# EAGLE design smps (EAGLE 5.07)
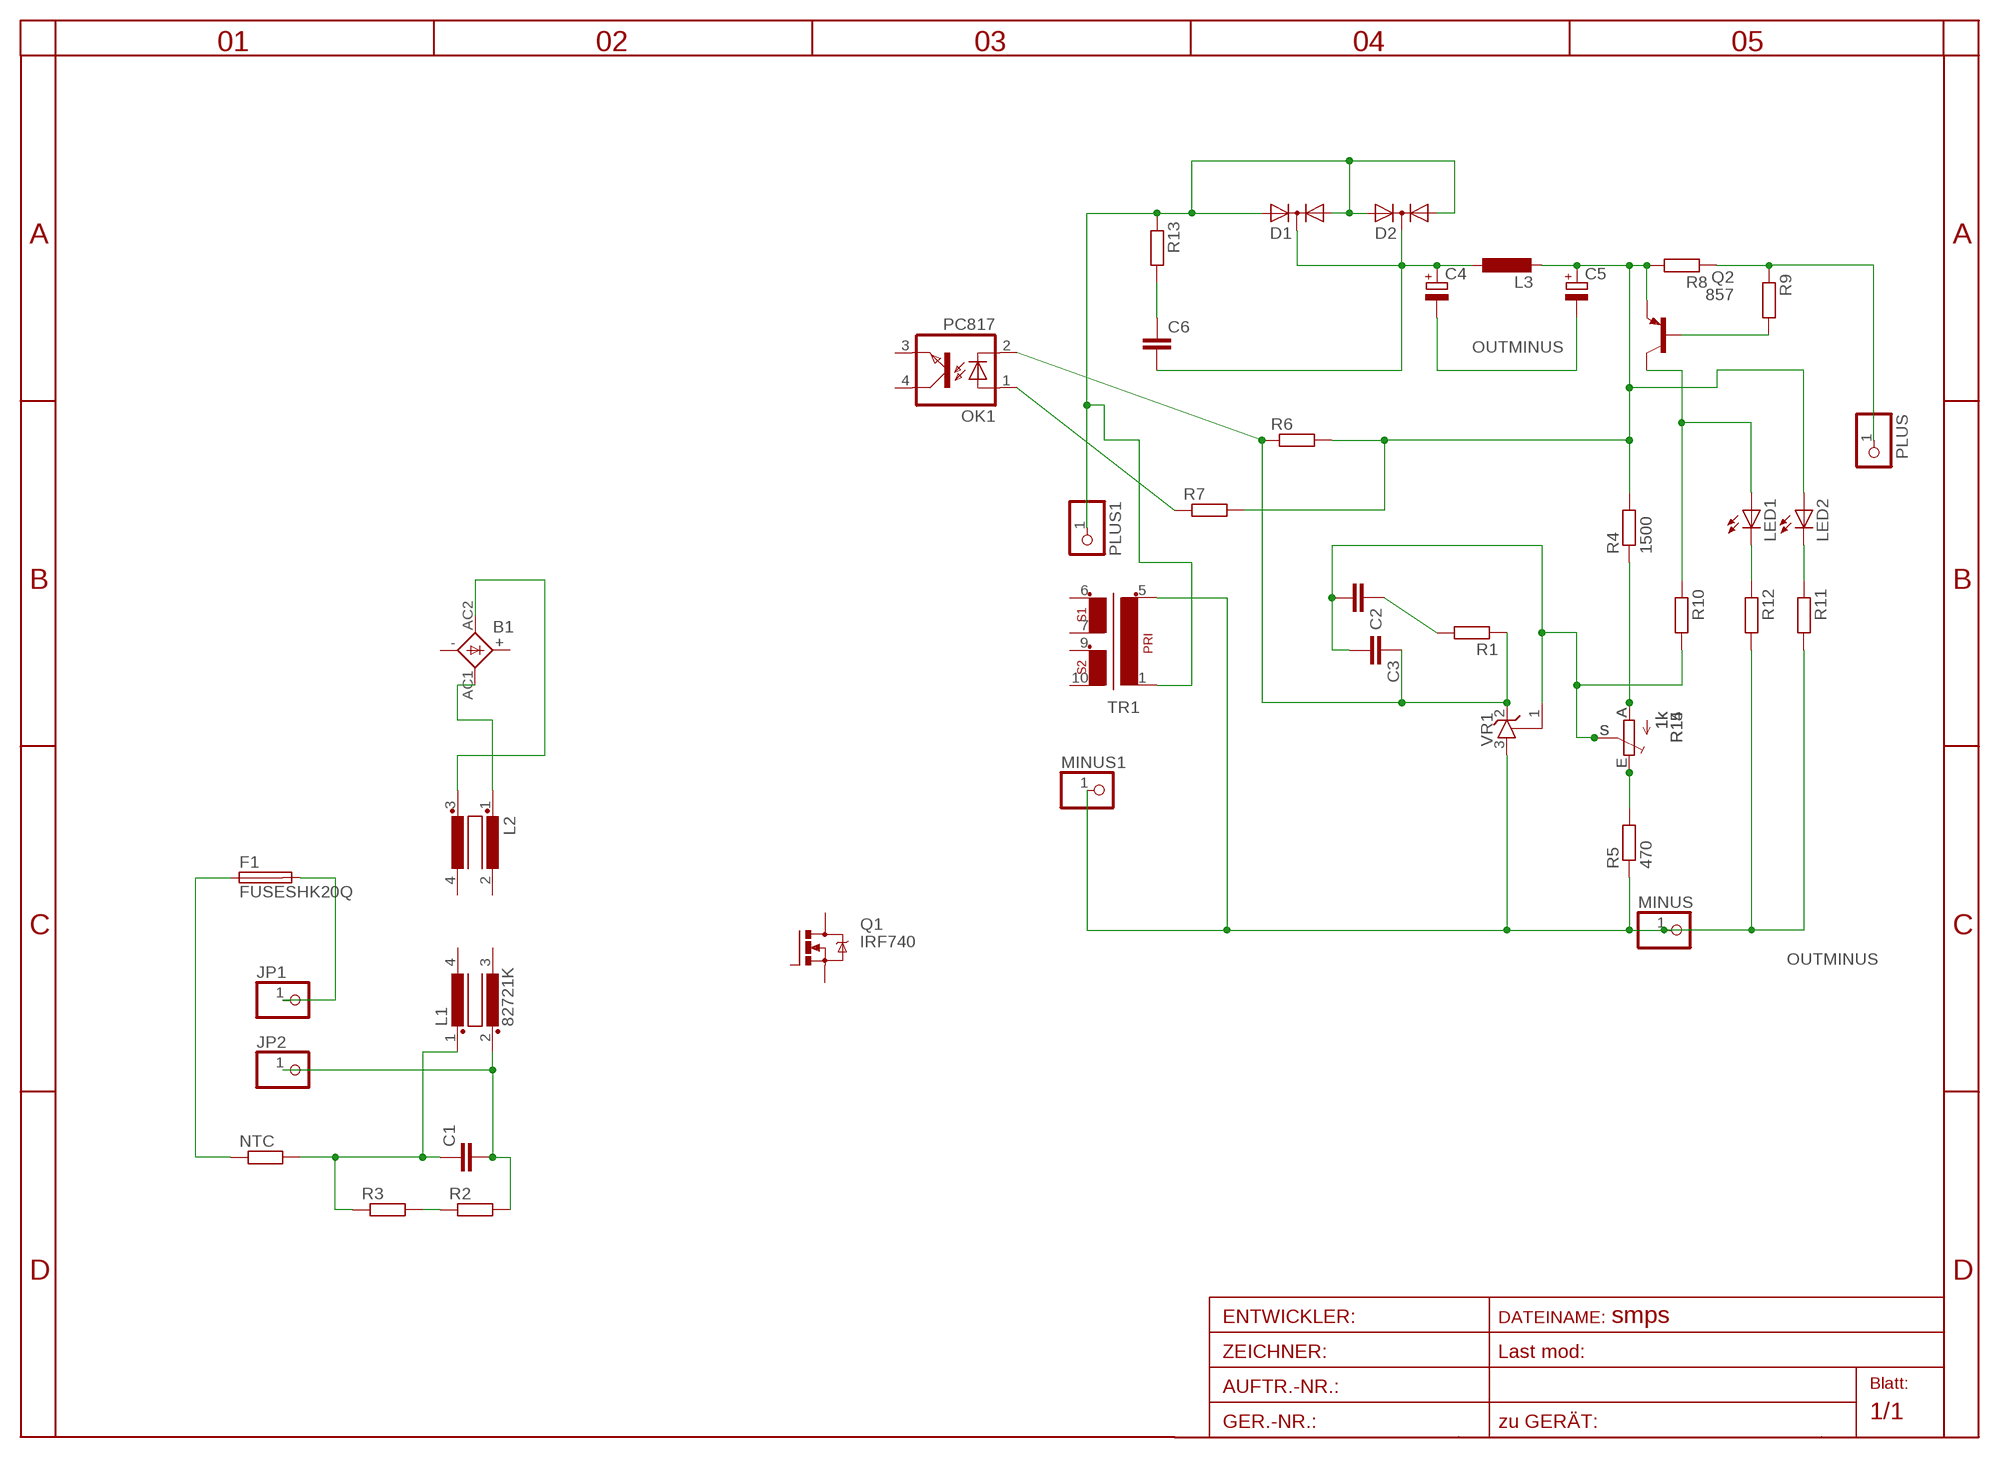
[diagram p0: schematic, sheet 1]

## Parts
B1  KBL  [KBL]
C1  C-EU150-084X183  [C150-084X183]
C2  C-EUC0805  [C0805]
C3  C-EUC0805  [C0805]
C4  CPOL-EUE5-8.5  [E5-8,5]
C5  CPOL-EUE5-8.5  [E5-8,5]
C6  C-EUC1206  [C1206]
D1  DIODE-2AC|CAIW220V  [IW220ABS]
D2  DIODE-2AC|CAIW220V  [IW220ABS]
F1  FUSESHK20Q  [SHK20Q]
JP1  PINHD-1X12MM2  [1X2MM2]
JP2  PINHD-1X12MM2  [1X2MM2]
L1  82721K  [82721K]
L2  R1405VB1  [B1]
L3  L-EU0204/5  [0204/5]
LED1  LED3MM  [LED3MM]
LED2  LED3MM  [LED3MM]
MINUS  PINHD-1X12MM2  [1X2MM2]
MINUS1  PINHD-1X11X0.4  [1X01]
NTC  R-EU_0204/7  [0204/7]
OK1  PC817  [DIL04]
PLUS  PINHD-1X12MM2  [1X2MM2]
PLUS1  PINHD-1X11X0.4  [1X01]
Q1  IRF740  [TO220BV]
Q2  857  BC857ASMD  [SOT23-BEC]
R1  R-EU_R0805  [R0805]
R2  R-EU_R1206  [R1206]
R3  R-EU_R1206  [R1206]
R4  1500  R-EU_R0805  [R0805]
R5  470  R-EU_R0805  [R0805]
R6  R-EU_R0805  [R0805]
R7  R-EU_R0805  [R0805]
R8  R-EU_R2010  [R2010]
R9  R-EU_R0805  [R0805]
R10  R-EU_R0805  [R0805]
R11  R-EU_R0805  [R0805]
R12  R-EU_R0805  [R0805]
R13  R-EU_R1206  [R1206]
R14  1k  TRIM_EU-S64W  [S64W]
R15  1k  TRIM_EU-CA6V  [CA6V]
TR1  EE20-2  [EE30GREEN]
VR1  TL431CLPSOT23  [SOT23]

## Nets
A: R4.1 R14.A R15.A
C1: LED1.A Q2.C R10.1
CPLUS: C4.+ C6.2 D1.C D2.C L3.1
E: R5.2 R14.E R15.E
N$1: C1.2 JP2.1 L1.2 R2.2
N$2: C1.1 L1.1 NTC.2 R3.1
N$3: F1.2A JP1.1
N$6: R2.1 R3.2
N$7: B1.AC2(AC1) L2.3
N$8: B1.AC1(AC2) L2.1
N$9: F1.1A NTC.1
N$11: C3.1 OK1.2(C) R1.1 R6.1 VR1.2(C)
N$12: OK1.1(A) R7.1
N$13: C2.1 R1.2
N$16: Q2.B R9.2
N$21: LED1.K(C) R12.1
N$23: LED2.K(C) R11.1
N$27: C6.1 R13.2
OUTMINUS: C4.- C5.- MINUS1.1 MINUS.1 R5.1 R11.2 R12.2 TR1.5 VR1.3(A)
OUTPLUS: PLUS.1 R8.1 R9.1
PLUS2: C5.+ L3.2 LED2.A Q2.E R4.2 R6.2 R7.2 R8.2
S: C2.2 C3.2 R10.2 R14.S R15.S VR1.1(R)
TOUT: D1.A1 D1.A2 D2.A1 D2.A2 PLUS1.1 R13.1 TR1.1
Unconnected: B1.+ B1.- L1.3 L1.4 L2.2 L2.4 OK1.3(EMIT) OK1.4(COL) Q1.D Q1.G Q1.S TR1.6 TR1.7 TR1.9 TR1.10

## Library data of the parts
B1 = rectifier:KBL: DIOTEC RECTIFIER
C1-C3 C6 = rcl:C-EU: CAPACITOR, European symbol
C4 C5 = rcl:CPOL-EU: POLARIZED CAPACITOR, European symbol
D1 D2 = diode:DIODE-2AC|CA: Dual DIODE Anode-Cathode|Cathode-Anode
F1 = fuse:FUSE: Fuse
JP1 JP2 MINUS MINUS1 PLUS PLUS1 = pinhead:PINHD-1X1: PIN HEADER
L1 = inductors:82721K: FILTER
L2 = inductor-nkl:R1405V: Übertrager (verlustarm) bis typ. 400kHz Power transformer (low loss) up to typ. 400kHz
L3 = rcl:L-EU: INDUCTOR, European symbol
LED1 LED2 = led:LED: LED
NTC R1-R13 = rcl:R-EU_: RESISTOR, European symbol
OK1 = optocoupler:PC817: SHARP OPTO COUPLER
Q1 = transistor-power:IRF740: N-CHANNEL MOS FET
Q2 = transistor-pnp:BC857*: PNP Transistror
R14 R15 = pot:TRIM_EU-: POTENTIOMETER
TR1 = trafo:EE20-2: TRANSFORMER 1 primary winding, 2 secondary windings ERA
VR1 = v-reg:TL431CLP: VOLTAGE REGULATOR

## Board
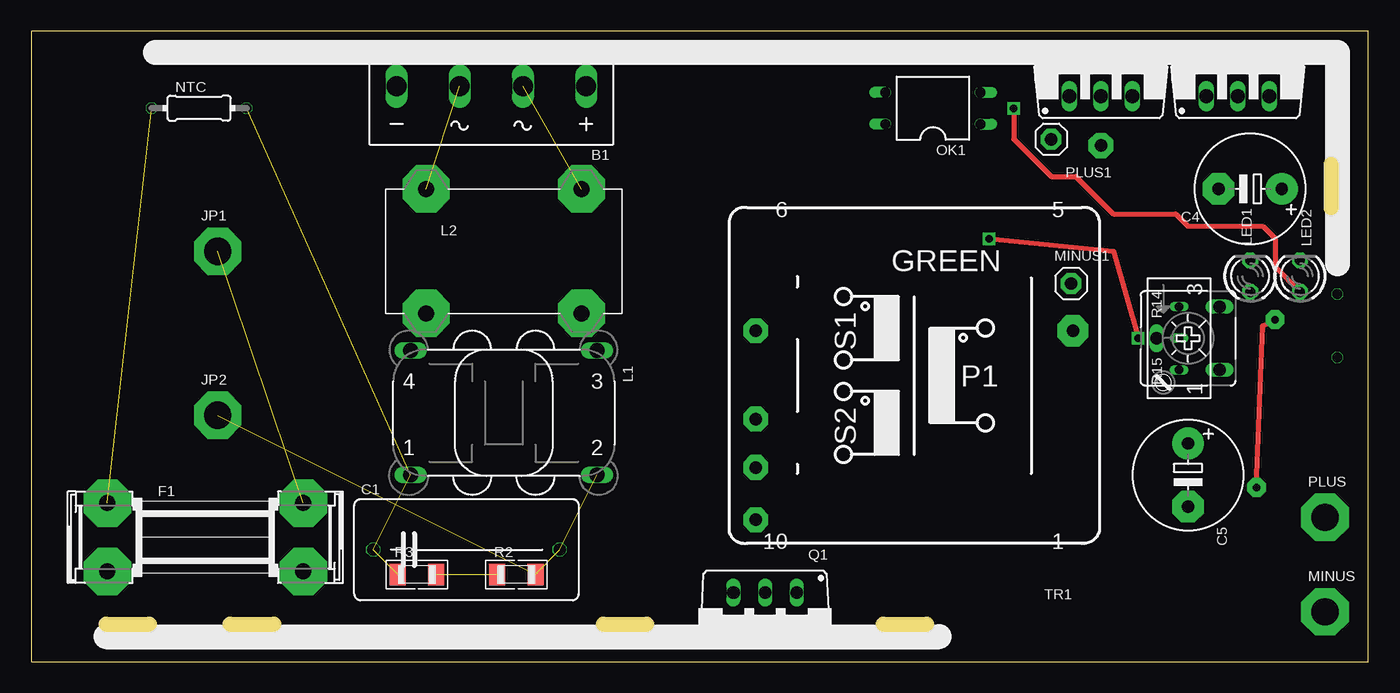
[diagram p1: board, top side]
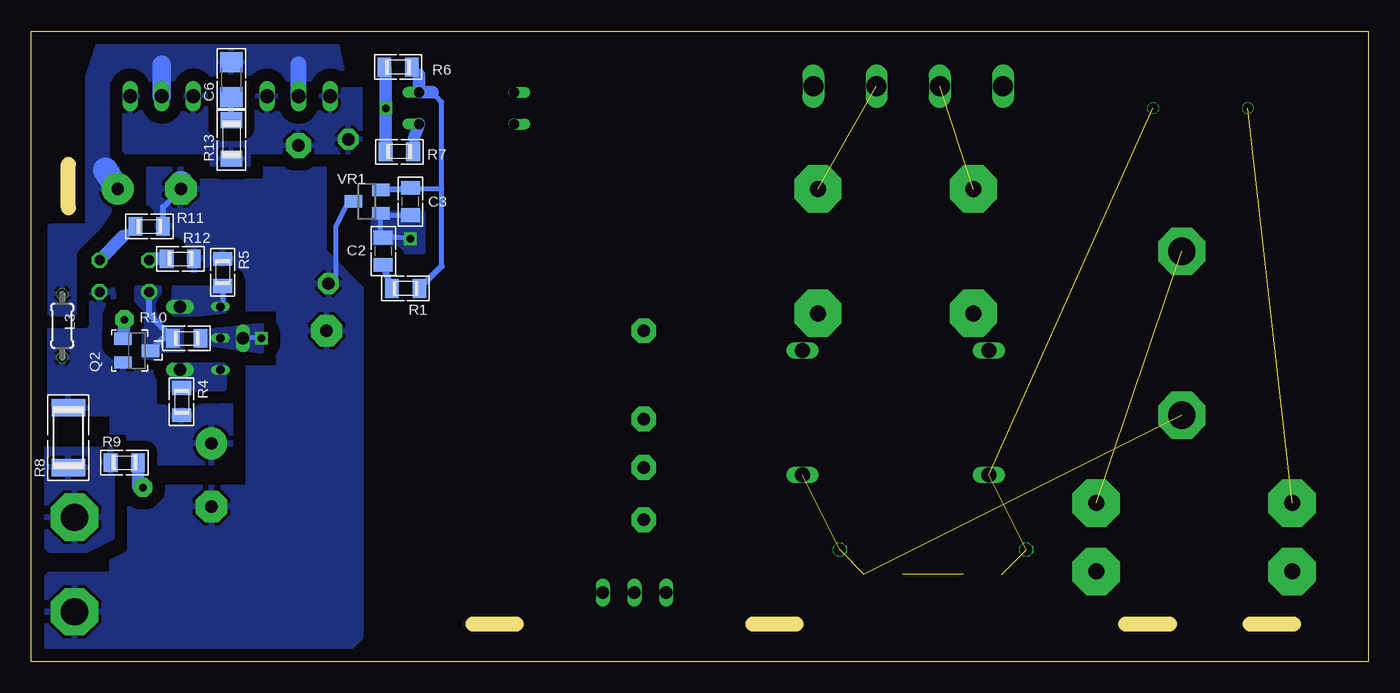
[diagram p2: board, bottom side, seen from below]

Size 107.5 x 50.7 mm. Coordinates in mm from the lower left corner, seen from the top.
Outline: 0,0 107.5,0 107.5,50.7 0,50.7 0,0
Copper layers (1*16): Top 0.035mm / dielectric 1.5mm / Bottom 0.035mm
Design rules "default": minimum track width 10mil, minimum drill 20mil, track to track 8mil, track to pad 8mil, pad to pad 8mil, via to via 8mil, smd to smd 8mil, copper to edge 40mil, drill to drill 8mil, minimum pad ring 1mil, minimum via ring 8mil, stop-mask expansion 4mil, vias tented up to drill 0mil, thermal gap 10mil
Milling: 5 lines

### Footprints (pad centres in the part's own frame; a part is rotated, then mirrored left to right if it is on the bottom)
KBL = drill 1.6 long: + -7.62,-1.27; - 7.62,-1.27; AC1 2.54,-1.27; AC2 -2.54,-1.27
C150-084X183 = drill 1.016 octagon: 1 -7.493,0; 2 7.493,0
C0805 = smd 1.1 x 1.5: 1 -1.1,0; 2 1.1,0
E5-8,5 = drill 1 pad 2.54 round: + -2.54,0 | drill 1 pad 2.54 octagon: - 2.54,0
C1206 = smd 1.6 x 1.8: 1 -1.4,0; 2 1.4,0
IW220ABS = drill 1.118 long: A1 -2.54,-2.54; A2 2.54,-2.54; C 0,-2.54
SHK20Q = drill 1.3 pad 3.81 octagon: 1A -7.874,2.75; 1B -7.874,-2.75; 2A 7.874,2.75; 2B 7.874,-2.75
1X2MM2 = drill 2.2 pad 3.81 octagon: 1 0,0
82721K = drill 1.194 long: 1 7.493,5.004; 2 -7.493,5.004; 3 -7.493,-5.004; 4 7.493,-5.004
B1 = drill 1.27 pad 3.81 octagon: 1 -6.25,5; 2 -6.25,-5; 3 6.25,5; 4 6.25,-5
0204/5 = drill 0.813 octagon: 1 -2.54,0; 2 2.54,0
LED3MM = drill 0.8 pad 1.27 octagon: A -1.27,0; K 1.27,0
1X01 = drill 1 pad 1.676 octagon: 1 0,0
0204/7 = drill 0.813 octagon: 1 -3.81,0; 2 3.81,0
DIL04 = drill 0.813 offset: 1 -1.27,-3.81; 2 1.27,-3.81; 3 1.27,3.81; 4 -1.27,3.81
TO220BV = drill 1.016 long: D 0,-2.54; G -2.54,-2.54; S 2.54,-2.54
SOT23-BEC = smd 1 x 1.4: B -0.95,-1.1; C 0,1.1; E 0.95,-1.1
R0805 = smd 1.1 x 1.5: 1 -1.1,0; 2 1.1,0
R1206 = smd 1.3 x 1.7: 1 -1.55,0; 2 1.55,0
R2010 = smd 1.4 x 2.7: 1 -2.4,0; 2 2.4,0
S64W = drill 0.7 long: A 2.54,1.27; E -2.54,1.27; S 0,1.27
CA6V = drill 1.016 long: A -2.54,-2.54; E 2.54,-2.54; S 0,2.54
EE30GREEN = drill 1 pad 2 octagon: 1 15,18.5; 6 -12.75,3.6; 7 -12.75,-3.5; 9 -12.75,-7.4; 10 -12.75,-11.6 | drill 1 pad 2.5 octagon: 5 12.75,3.6
SOT23 = smd 1 x 1.4: 1 -0.95,-1.1; 2 0.95,-1.1; 3 0,1.1

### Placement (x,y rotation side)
B1  37,45 180 top
C1  35,9 0 top
C2  79.2,33 90 bottom
C3  77,37 270 bottom
C4  98,38 180 top
C5  93,15 270 top
C6  91.4,46.8 90 bottom
D1  97,48 0 top
D2  86,48 0 top
F1  14,10 0 top
JP1  15,33 0 top
JP2  15,19.8 0 top
L1  38,20 180 top
L2  38,33 0 top
L3  105,27 270 bottom
LED1  98,31 90 top
LED2  102,31 90 top
MINUS  104,4 0 top
MINUS1  83.6,30.4 0 top
NTC  13.5,44.5 0 top
OK1  72.5,44.5 90 top
PLUS  104,11.6 0 top
PLUS1  82,42 0 top
Q1  59,3 180 top
Q2  99,25 270 bottom
R1  77.4,30 180 bottom
R2  39,7 0 top
R3  31,7 0 top
R4  95.4,20.9 270 bottom
R5  92.1,31.3 270 bottom
R6  78,47.8 180 bottom
R7  77.9,41 180 bottom
R8  104.5,18 90 bottom
R9  100,16 0 bottom
R10  95,26 0 bottom
R11  98,35 0 bottom
R12  95.5,32.4 0 bottom
R13  91.4,42 90 bottom
R14  91,26 270 top
R15  93,26 90 top
TR1  71,23 0 top
VR1  80.5,37 90 bottom

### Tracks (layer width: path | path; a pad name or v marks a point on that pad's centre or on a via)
A
  pour Bottom (isolate 1.016, rank 2, no thermals): 92,23.8 96.2,23.8 96.2,21.9 92,22
C1
  Bottom 0.5: LED1.A 98,27.9 R10.1 96.9,26 Q2.C
  pour Bottom (isolate 0.8, rank 5, no thermals): 97,30 99,30 99,24 95,24 95,27 97,27
CPLUS
  Bottom 1.27: D2.C 86,48
  Bottom 1.5: D1.C 97,48
  Bottom 2: C4.+ 101.54,39.54
  pour Bottom (isolate 1, rank 3): 83,50 102,50 103,47 103,35 106,35 106,28 104,28 104,33 102,35 100,38 101.1,45.8 82.1,45.8
E
  Bottom 0.406: R5.2 92.1,28.71 R14.E
  pour Bottom (isolate 1, rank 2, no thermals): 96,28 92,28 92,30 96,30
N$1  (3 unrouted)
N$2  (3 unrouted)
N$3  (1 unrouted)
N$6  (1 unrouted)
N$7  (1 unrouted)
N$8  (1 unrouted)
N$9  (1 unrouted)
N$11
  Bottom 0.406: 77.15,37.95 C3.1 76.9,38 74.5,38 | 74.5,31.8 74.5,38 | 76.31,47.21 R6.1 | 75.23,45.77 74.5,45 74.5,38
  Bottom 0.5: 77.15,37.95 VR1.2 | R1.1 74.5,31.8
  Bottom 1: 76.31,47.21 OK1.2 75.23,45.77
N$12
  Bottom 0.5: R7.1 76.7,42.14
  Bottom 1: 76.7,42.14 OK1.1
N$13
  Bottom 0.5: R1.2 C2.1
N$16  (via drill 0.6 pad 1.5)
  Top 0.406: v98.5,14 99,27 v100,27.5
  Bottom 0.406: v98.5,14 98.9,14.1 | v100,27.5 100,27.05
  Bottom 1: 98.9,14.1 R9.2 | 100,27.05 Q2.B
N$21
  Bottom 0.406: 97.87,32.4 LED1.K
  Bottom 1: R12.1 97.87,32.4
N$23
  Bottom 0.5: R11.1 100.1,34.2
  Bottom 1: 100.1,34.2 LED2.K
N$27
  Bottom 0.5: R13.2 C6.1
OUTMINUS
  Bottom 0.406: VR1.3 82,37 83,35 83,31 MINUS1.1
  Bottom 0.5: R11.2 96.9,36.56 C4.-
  Bottom 2: C4.- 95.46,38.46
  pour Bottom (isolate 1, rank 3): 98,40 84,40 84,33 81,30 81,2 82,1 106,1 107,2 107,6 106,7 101,7 101,14 90,14 90,31 96,31 98,36
OUTPLUS
  pour Bottom (isolate 1): 107,17 107,10 106,9 103,9 101,10 101,17
PLUS2  (via drill 0.6)
  Top 0.406: v79,44.5 79,42 82,39 84,39 87,36 92,36 93,35 99,35 100,34 100,31.73 LED2.A
  Bottom 0.406: 79,47.7 R6.2
  Bottom 0.5: R4.2 95.9,20
  Bottom 1: R7.2 v79,44.5 79,47.7
  pour Bottom (isolate 1, rank 4): 102,30 106,27 106,21 105,20 101,20 101,16 91,16 90.7,23.7 99.7,23.5 101,30
S  (via drill 0.6)
  Top 0.406: v77,34 87,33 v89,26
  Bottom 0.406: C3.2 79.25,35.9 VR1.1 79.4,34.3 C2.2 77.9,34.1 v77,34 | v89,26 89.9,26.04 R15.S
  pour Bottom (isolate 1, no thermals): 89,27 93.4,26.5 93.4,25.6 89,25
  pour Bottom (isolate 1, rank 3, no thermals): 76,36 80,36 80,33 76,33
TOUT
  pour Bottom (isolate 1, rank 2): 81,46 100,46 100,41 93,41 93,40 90,40 90,41 81,41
